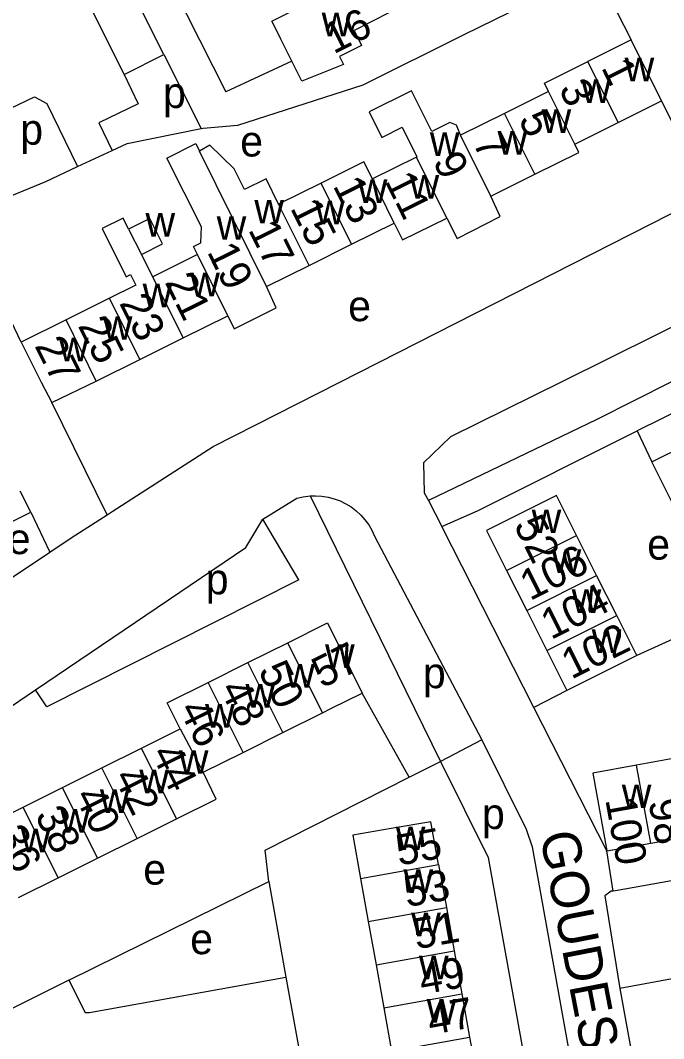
# Model space of a CAD drawing. Extents: x 157794 to 159375, y 380877 to 382306.
# Drawn here: x 158270.1 to 158354, y 381414.5 to 381547.1 of the extents above; entities that cross this region are included whole.
import ezdxf

# ---------------------------------------------------------------- set-up
doc = ezdxf.new("R2010")
doc.units = 0
for name, color, linetype in [('BLT_Basislijn', 7, 'Continuous'), ('BLT_Bebouwing', 7, 'Continuous'), ('BLT_Centroide', 7, 'Continuous'), ('BLT_Huisnummer', 7, 'Continuous'), ('BLT_Huisnummer_ tussenligend', 7, 'Continuous'), ('BLT_Onderverdeling_panden', 7, 'Continuous'), ('BLT_Straatnaam', 7, 'Continuous')]:
    doc.layers.add(name, color=color, linetype=linetype)

msp = doc.modelspace()

# ---------------------------------------------------------------- linework, layer by layer
at = {"layer": 'BLT_Basislijn'}
for p, q in [((158288.84, 381542.71), (158283.87, 381552.55)), ((158328, 381545.32), (158345.15, 381553.71)), ((158345.15, 381553.71), (158349.78, 381544.59)), ((158288.84, 381542.71), (158293.73, 381533.04)), ((158305.53, 381541.83), (158296.92, 381537.82)), ((158359.89, 381524.44), (158353.74, 381536.64)), ((158270.26, 381505.23), (158262.35, 381521.59)), ((158281.44, 381482.74), (158274.24, 381497.35)), ((158350.57, 381493.67), (158352.48, 381489.64)), ((158301.75, 381482.17), (158306.2, 381484.88)), ((158307.9, 381485.18), (158324.91, 381450.59)), ((158323.33, 381484.58), (158325.08, 381481.18)), ((158271.51, 381483.07), (158273.97, 381477.85)), ((158276.91, 381479.8), (158281.44, 381482.74)), ((158306.44, 381474.26), (158301.75, 381482.17)), ((158337.08, 381457.61), (158325.08, 381481.18)), ((158273.97, 381477.85), (158276.91, 381479.8)), ((158316.33, 381479.94), (158330.29, 381453.4)), ((158250.97, 381462.56), (158273.97, 381477.85)), ((158357.53, 381467.58), (158350.52, 381464.39)), ((158341.38, 381459.83), (158337.08, 381457.61)), ((158320.82, 381448.54), (158314.72, 381459.5)), ((158346.6, 381438.92), (158337.08, 381457.61)), ((158330.29, 381453.4), (158324.91, 381450.59)), ((158320.82, 381448.54), (158324.91, 381450.59)), ((158347.43, 381433.69), (158346.6, 381438.92)), ((158276.46, 381422.1), (158302.53, 381434.95)), ((158302.53, 381434.95), (158304.74, 381422.48)), ((158375.43, 381425.92), (158348.3, 381421.02)), ((158276.46, 381422.1), (158257.72, 381412.71))]:
    msp.add_line(p, q, dxfattribs=at)
for points in [[(158288.35, 381554.77), (158296.92, 381537.82)], [(158278.73, 381550), (158283.66, 381540.09)], [(158298.47, 381533.48), (158314.83, 381538.73), (158328, 381545.32)], [(158432.05, 381545.11), (158427.59, 381543.14), (158340.66, 381500), (158326.22, 381492.89), (158322.69, 381489.48), (158322.78, 381485.57), (158323.33, 381484.58)], [(158432.05, 381545.11), (158434.63, 381540.01), (158424.45, 381534.91), (158354.95, 381500), (158345.29, 381495.16), (158323.33, 381484.58)], [(158283.66, 381540.09), (158288.84, 381542.71)], [(158283.66, 381540.09), (158285.49, 381536.25), (158280.37, 381533.81), (158282.12, 381530.2)], [(158253.07, 381528.17), (158271.99, 381537.18), (158273.59, 381536.3), (158277.59, 381528.09)], [(158282.12, 381530.2), (158284.08, 381531.11), (158293.73, 381533.04)], [(158293.73, 381533.04), (158293.97, 381533.09), (158298.47, 381533.48)], [(158277.59, 381528.09), (158282.12, 381530.2)], [(158262.35, 381521.59), (158273.46, 381526.17), (158277.59, 381528.09)], [(158281.44, 381482.74), (158282.1, 381483.17), (158295.26, 381491.61), (158311.81, 381500), (158359.89, 381524.44)], [(158402.32, 381519.33), (158363.43, 381500), (158350.57, 381493.67)], [(158325.08, 381481.18), (158329.73, 381483.23), (158350.14, 381493.45), (158350.57, 381493.67)], [(158306.2, 381484.88), (158307, 381485.07), (158307.9, 381485.18)], [(158307.9, 381485.18), (158308.63, 381485.21), (158309.45, 381485.15), (158310.26, 381485.02), (158311.06, 381484.81), (158311.83, 381484.53), (158312.57, 381484.17), (158313.27, 381483.74), (158313.92, 381483.24), (158314.52, 381482.68), (158315.07, 381482.07), (158315.56, 381481.41), (158315.97, 381480.7), (158316.33, 381479.94)], [(158272.11, 381459.9), (158299.52, 381478.46), (158301.75, 381482.17)], [(158306.44, 381474.26), (158273.58, 381457.69), (158272.11, 381459.9)], [(158246.12, 381442.3), (158272.11, 381459.9)], [(158330.29, 381453.4), (158336.09, 381441.77), (158336.86, 381439.44), (158345.76, 381389.92), (158345.88, 381387.23), (158345.46, 381386.19), (158342.93, 381384.09), (158340.9, 381383.7)], [(158324.91, 381450.59), (158331.15, 381438.09), (158340.9, 381383.7)], [(158302.53, 381434.95), (158302.07, 381439.03), (158320.82, 381448.54)], [(158389.04, 381441.08), (158388.65, 381441.01), (158347.73, 381433.71), (158347.43, 381433.69)], [(158347.43, 381433.69), (158347.15, 381433.68), (158346.36, 381433.08), (158348.3, 381421.02)], [(158276.46, 381422.1), (158278.6, 381417.87), (158279.13, 381417.87), (158304.74, 381422.48)], [(158304.74, 381422.48), (158307.35, 381408.17), (158309.18, 381398.15), (158310.27, 381392.12)], [(158348.3, 381421.02), (158353.18, 381394.28), (158353.76, 381394.39)]]:
    msp.add_lwpolyline(points, dxfattribs=at)
at = {"layer": 'BLT_Bebouwing'}
for p, q in [((158305.53, 381541.83), (158304.1, 381544.7)), ((158349.78, 381544.59), (158344.12, 381541.78)), ((158353.74, 381536.64), (158349.78, 381544.59)), ((158338.99, 381537.88), (158333.25, 381535.03)), ((158348.07, 381533.82), (158353.74, 381536.64)), ((158333.25, 381535.03), (158327.51, 381532.18)), ((158342.41, 381531.01), (158348.07, 381533.82)), ((158321.77, 381529.33), (158316.03, 381526.48)), ((158331.46, 381524.24), (158337.2, 381527.09)), ((158309.37, 381525.95), (158303.81, 381523.19)), ((158313.33, 381517.97), (158318.88, 381520.73)), ((158307.77, 381515.21), (158313.33, 381517.97)), ((158293.21, 381516.62), (158287.39, 381513.73)), ((158302.21, 381512.45), (158307.77, 381515.21)), ((158281.74, 381510.93), (158276.09, 381508.12)), ((158276.09, 381508.12), (158270.26, 381505.23)), ((158285.7, 381502.96), (158291.35, 381505.77)), ((158280.04, 381500.15), (158285.7, 381502.96)), ((158274.24, 381497.35), (158280.04, 381500.15)), ((158352.48, 381489.64), (158358.14, 381492.46)), ((158271.51, 381483.07), (158270.13, 381485.82)), ((158345.27, 381474.83), (158342.65, 381480.04)), ((158333.54, 381475.47), (158336.15, 381470.26)), ((158347.89, 381469.62), (158345.27, 381474.83)), ((158336.15, 381470.26), (158338.77, 381465.05)), ((158350.52, 381464.39), (158347.89, 381469.62)), ((158299.81, 381463.47), (158304.99, 381466.05)), ((158338.77, 381465.05), (158341.38, 381459.83)), ((158294.62, 381460.89), (158299.81, 381463.47)), ((158285.93, 381452.32), (158290.97, 381454.82)), ((158299.18, 381451.75), (158304.36, 381454.34)), ((158280.78, 381449.76), (158285.93, 381452.32)), ((158293.99, 381449.17), (158299.18, 381451.75)), ((158356.21, 381451.14), (158350.49, 381450.11)), ((158275.63, 381447.2), (158280.78, 381449.76)), ((158270.48, 381444.64), (158275.63, 381447.2)), ((158265.33, 381442.08), (158270.48, 381444.64)), ((158285.36, 381440.55), (158290.51, 381443.11)), ((158280.21, 381437.99), (158285.36, 381440.55)), ((158346.6, 381438.92), (158352.32, 381439.94)), ((158352.32, 381439.94), (158358.04, 381440.97)), ((158275.06, 381435.43), (158280.21, 381437.99)), ((158324.67, 381437.17), (158325.68, 381431.54)), ((158269.91, 381432.87), (158275.06, 381435.43)), ((158314.49, 381435.34), (158315.5, 381429.72)), ((158325.68, 381431.54), (158326.69, 381425.92)), ((158315.5, 381429.72), (158316.51, 381424.09)), ((158326.69, 381425.92), (158327.7, 381420.3)), ((158316.51, 381424.09), (158317.51, 381418.47)), ((158327.7, 381420.3), (158328.71, 381414.67)), ((158317.51, 381418.47), (158318.52, 381412.84)), ((158328.71, 381414.67), (158329.72, 381409.05))]:
    msp.add_line(p, q, dxfattribs=at)
for points in [[(158304.1, 381544.7), (158303.3, 381546.3), (158302.93, 381547.05), (158305.97, 381548.57)], [(158320.65, 381549.39), (158313.64, 381545.83), (158314.61, 381543.88), (158311.73, 381542.44), (158312.26, 381541.38), (158306.83, 381539.24), (158305.53, 381541.83)], [(158338.99, 381537.88), (158338.46, 381538.97), (158344.12, 381541.78)], [(158327.51, 381532.18), (158327, 381533.48), (158326.15, 381533.84), (158323.78, 381532.67), (158321.14, 381537.98), (158315.62, 381535.24), (158317.27, 381531.9), (158319.92, 381533.22), (158321.84, 381529.36), (158321.77, 381529.33)], [(158293.21, 381516.62), (158292.69, 381517.67), (158293.67, 381518.15), (158293.75, 381520.25), (158289.25, 381529.19), (158293.01, 381531.1), (158293.51, 381530.12)], [(158303.81, 381523.19), (158302.2, 381526.5), (158299.37, 381525.09), (158298, 381527.79), (158294.86, 381530.89), (158293.51, 381530.12)], [(158337.2, 381527.09), (158342.94, 381529.94), (158342.41, 381531.01)], [(158316.03, 381526.48), (158314.92, 381528.71), (158309.37, 381525.95)], [(158325.72, 381521.39), (158327.09, 381518.71), (158332.7, 381521.57), (158331.46, 381524.24)], [(158284.24, 381519.94), (158283.52, 381521.39), (158280.8, 381520.04), (158283.92, 381513.75), (158284.5, 381514.04), (158285.19, 381512.64), (158281.74, 381510.93)], [(158285.94, 381516.65), (158288.67, 381518.01), (158287.02, 381521.32), (158284.24, 381519.94)], [(158318.88, 381520.73), (158319.98, 381518.53), (158325.72, 381521.39)], [(158287.39, 381513.73), (158285.94, 381516.65)], [(158297.17, 381508.66), (158298.01, 381506.96), (158303.49, 381509.68), (158302.21, 381512.45)], [(158291.35, 381505.77), (158297.17, 381508.66)], [(158270.26, 381505.23), (158272.86, 381500), (158274.24, 381497.35)], [(158357.06, 381480.4), (158356.98, 381480.58), (158354.69, 381485.19), (158352.48, 381489.64)], [(158342.65, 381480.04), (158340.05, 381485.22), (158330.93, 381480.68), (158333.54, 381475.47)], [(158257.5, 381479.5), (158258.2, 381478.11), (158260.43, 381473.63), (158267.67, 381477.26), (158266.11, 381480.37), (158271.51, 381483.07)], [(158304.99, 381466.05), (158310.18, 381468.63), (158314.72, 381459.5)], [(158350.52, 381464.39), (158345.83, 381462.05), (158341.38, 381459.83)], [(158290.97, 381454.82), (158289.28, 381458.24), (158294.62, 381460.89)], [(158309.54, 381456.92), (158310.72, 381457.51), (158314.72, 381459.5)], [(158304.36, 381454.34), (158309.54, 381456.92)], [(158290.51, 381443.11), (158295.66, 381445.68), (158293.99, 381449.17)], [(158350.49, 381450.11), (158344.77, 381449.08), (158346.6, 381438.92)], [(158324.67, 381437.17), (158323.67, 381442.71), (158318.47, 381441.86), (158313.48, 381440.96), (158314.49, 381435.34)]]:
    msp.add_lwpolyline(points, dxfattribs=at)
at = {"layer": 'BLT_Onderverdeling_panden'}
for p, q in [((158348.07, 381533.82), (158344.12, 381541.78)), ((158342.41, 381531.01), (158338.99, 381537.88)), ((158337.2, 381527.09), (158333.25, 381535.03)), ((158331.46, 381524.24), (158327.51, 381532.18)), ((158302.21, 381512.45), (158293.51, 381530.12)), ((158325.72, 381521.39), (158321.77, 381529.33)), ((158318.88, 381520.73), (158316.03, 381526.48)), ((158313.33, 381517.97), (158309.37, 381525.95)), ((158307.77, 381515.21), (158303.81, 381523.19)), ((158284.24, 381519.94), (158285.94, 381516.65)), ((158297.17, 381508.66), (158293.21, 381516.62)), ((158291.35, 381505.77), (158287.39, 381513.73)), ((158285.7, 381502.96), (158281.74, 381510.93)), ((158280.04, 381500.15), (158276.09, 381508.12)), ((158333.54, 381475.47), (158342.65, 381480.04)), ((158336.15, 381470.26), (158345.27, 381474.83)), ((158338.77, 381465.05), (158347.89, 381469.62)), ((158309.54, 381456.92), (158304.99, 381466.05)), ((158304.36, 381454.34), (158299.81, 381463.47)), ((158299.18, 381451.75), (158294.62, 381460.89)), ((158290.97, 381454.82), (158293.99, 381449.17)), ((158290.51, 381443.11), (158285.93, 381452.32)), ((158285.36, 381440.55), (158280.78, 381449.76)), ((158352.32, 381439.94), (158350.49, 381450.11)), ((158280.21, 381437.99), (158275.63, 381447.2)), ((158275.06, 381435.43), (158270.48, 381444.64)), ((158314.49, 381435.34), (158324.67, 381437.17)), ((158315.5, 381429.72), (158325.68, 381431.54)), ((158316.51, 381424.09), (158326.69, 381425.92)), ((158317.51, 381418.47), (158327.7, 381420.3)), ((158318.52, 381412.84), (158328.71, 381414.67))]:
    msp.add_line(p, q, dxfattribs=at)

# ---------------------------------------------------------------- texts
at = {"layer": 'BLT_Centroide'}
for s, p in [('w', (158309.43, 381545.06)), ('w', (158348.92, 381539.2)), ('w', (158343.27, 381536.39)), ('p', (158288.74, 381535.73)), ('w', (158338.09, 381532.48)), ('p', (158270.12, 381530.95)), ('w', (158332.36, 381529.64)), ('e', (158298.8, 381529.41)), ('w', (158323.53, 381529.47)), ('w', (158314.12, 381523.34)), ('w', (158320.88, 381523.92)), ('w', (158300.64, 381520.69)), ('w', (158308.56, 381520.58)), ('w', (158286.45, 381518.97)), ('w', (158295.73, 381518.56)), ('w', (158292.28, 381511.19)), ('w', (158286.08, 381509.77)), ('e', (158312.88, 381507.95)), ('w', (158280.89, 381505.53)), ('w', (158275.16, 381502.72)), ('w', (158336.8, 381480.34)), ('e', (158268.5, 381477.6)), ('e', (158351.87, 381476.88)), ('w', (158339.41, 381475.16)), ('p', (158294.31, 381472.36)), ('w', (158342.02, 381469.94)), ('w', (158344.63, 381464.72)), ('w', (158309.86, 381462.77)), ('w', (158304.67, 381460.19)), ('p', (158322.62, 381460.13)), ('w', (158299.48, 381457.61)), ('w', (158294.22, 381454.98)), ('w', (158290.8, 381448.98)), ('w', (158285.64, 381446.44)), ('w', (158280.5, 381443.88)), ('w', (158348.55, 381444.5)), ('w', (158275.34, 381441.31)), ('p', (158330.32, 381441.78)), ('w', (158270.2, 381438.75)), ('w', (158319.08, 381439.03)), ('e', (158286.16, 381434.53)), ('w', (158320.09, 381433.44)), ('w', (158321.09, 381427.81)), ('e', (158292.28, 381425.47)), ('w', (158322.1, 381422.19)), ('w', (158323.11, 381416.56))]:
    msp.add_text(s, height=4, dxfattribs=at).set_placement(p)
at = {"layer": 'BLT_Huisnummer'}
for s, rotation, p in [('16', 26.5395, (158310.97, 381542.7)), ('1', 296.4082, (158345.82, 381541.01)), ('5', 296.4082, (158335.02, 381534.24)), ('9', 296.4082, (158323.86, 381528.79)), ('13', 296.4082, (158310.83, 381525.62)), ('17', 296.4082, (158299.79, 381519.88)), ('21', 296.4082, (158288.9, 381513.06)), ('27', 296.4082, (158271.94, 381504.76)), ('52', 296.6299, (158334.41, 381481.4)), ('106', 26.521, (158336.58, 381471.46)), ('102', 26.521, (158341.98, 381461.23)), ('57', 26.5061, (158309.45, 381460.06)), ('50', 296.4394, (158301.09, 381462.44)), ('46', 296.4394, (158290.75, 381457.41)), ('42', 296.4394, (158282.24, 381448.59)), ('100', 280.2062, (158346.39, 381445.62)), ('38', 296.4394, (158271.98, 381443.57)), ('55', 10.1748, (158319.48, 381437)), ('49', 10.1748, (158322.5, 381420.2))]:
    msp.add_text(s, height=4, rotation=rotation, dxfattribs=at).set_placement(p)
at = {"layer": 'BLT_Huisnummer_ tussenligend'}
for s, rotation, p in [('3', 296.4082, (158340.28, 381538.23)), ('7', 296.4082, (158329.06, 381531.25)), ('11', 296.4082, (158317.59, 381526.23)), ('15', 296.4082, (158305.27, 381522.71)), ('19', 296.4082, (158294.42, 381517.01)), ('23', 296.4082, (158282.97, 381510.33)), ('25', 296.4082, (158277.59, 381507.37)), ('104', 26.521, (158339.32, 381466.39)), ('48', 296.4394, (158296.05, 381460.05)), ('44', 296.4394, (158287.13, 381451.65)), ('40', 296.4394, (158277.14, 381446.09)), ('98', 280.2062, (158352.02, 381445.38)), ('36', 296.4394, (158266.86, 381441.07)), ('53', 10.1748, (158320.52, 381431.59)), ('51', 10.1748, (158321.76, 381426.1)), ('47', 10.1748, (158323.59, 381414.94))]:
    msp.add_text(s, height=4, rotation=rotation, dxfattribs=at).set_placement(p)
at = {"layer": 'BLT_Straatnaam'}
msp.add_text('GOUDESTEIN', height=5, rotation=280.959, dxfattribs=at).set_placement((158337.85, 381441.08))

doc.saveas('drawing.dxf')
